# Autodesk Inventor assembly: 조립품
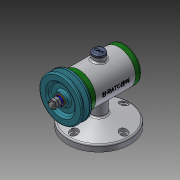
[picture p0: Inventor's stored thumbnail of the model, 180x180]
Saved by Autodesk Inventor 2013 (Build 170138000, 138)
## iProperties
Created: 2018-12
Part Number: 조립품
Document SubType Name: Assembly
Designer: hana-cad23
Author: hana-cad23
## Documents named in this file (15)
- C:\Documents and Settings\hana-cad23\바탕 화면\481207V1003\조립품.iam
- C:\Documents and Settings\hana-cad23\바탕 화면\481207V1003\스프링와셔 8.ipt
- C:\Documents and Settings\hana-cad23\바탕 화면\481207V1003\앞커버.ipt
- C:\Documents and Settings\hana-cad23\바탕 화면\481207V1003\오일 실 15 25 7.ipt
- C:\Documents and Settings\hana-cad23\바탕 화면\481207V1003\와셔 8x17.ipt
- C:\Documents and Settings\hana-cad23\바탕 화면\481207V1003\축.ipt
- C:\Documents and Settings\hana-cad23\바탕 화면\481207V1003\키 3 x 3 x 12.ipt
- C:\Documents and Settings\hana-cad23\바탕 화면\481207V1003\V벨트풀리.ipt
- C:\Documents and Settings\hana-cad23\바탕 화면\481207V1003\고무캡.ipt
- C:\Documents and Settings\hana-cad23\바탕 화면\481207V1003\너트 M8.ipt
- 너트 M8.ipt
- C:\Documents and Settings\hana-cad23\바탕 화면\481207V1003\뒤커버.ipt
- C:\Documents and Settings\hana-cad23\바탕 화면\481207V1003\베어링 15 x 32 x 9.ipt
- C:\Documents and Settings\hana-cad23\바탕 화면\481207V1003\본체.ipt
- C:\Documents and Settings\hana-cad23\바탕 화면\481207V1003\볼트 M4 x 12.ipt
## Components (2 placed, 2 different names)
1. V벨트풀리:1
2. 고무캡:1
